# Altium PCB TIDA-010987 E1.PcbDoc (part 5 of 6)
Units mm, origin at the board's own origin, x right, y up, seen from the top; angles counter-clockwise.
Board outline 154.15 x 103.76 mm, 4 copper layers (5V, GND, MidSupply, -5V), stack 1.787 mm thick; 92 components, 52 nets, 1640 pads, 56 vias.
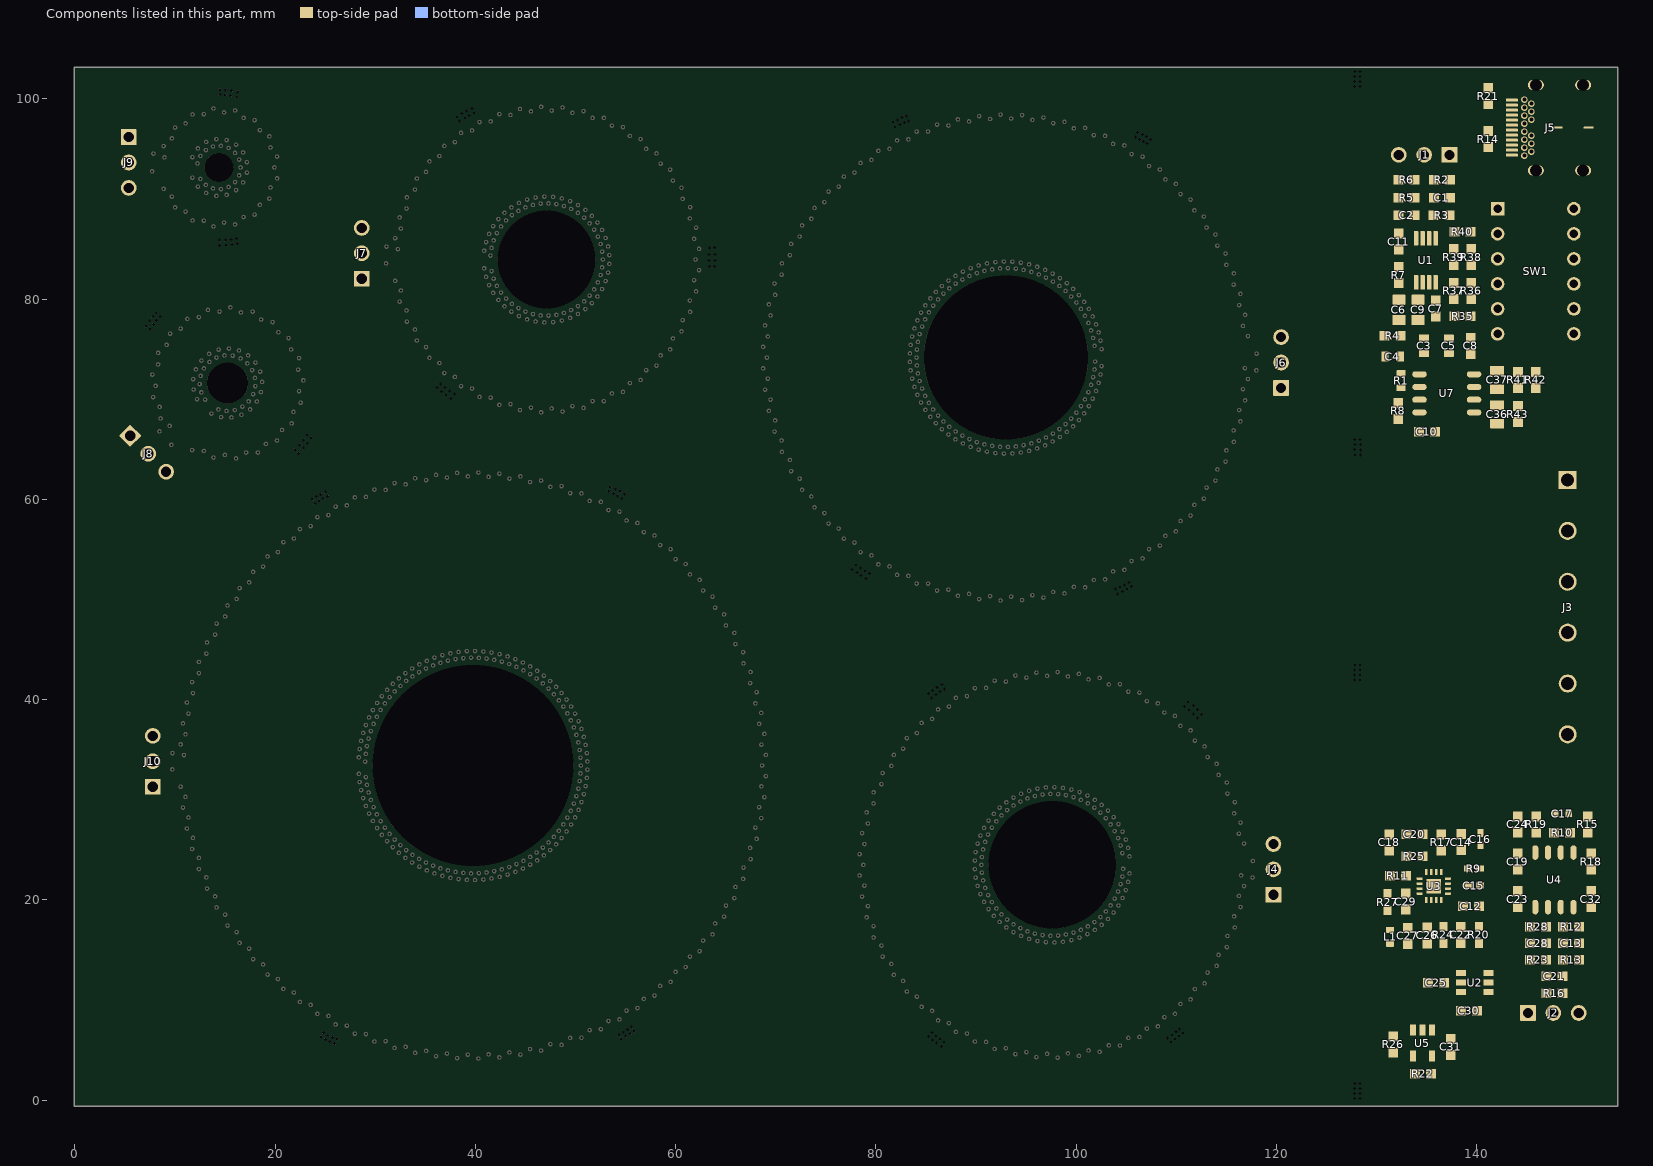
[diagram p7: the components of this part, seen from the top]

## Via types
v1: diameter 0.61, hole 0.203, 5V to -5V, tented both sides, 52 vias
v2: diameter 0.5, hole 0.2, 5V to -5V, tented both sides, 4 vias

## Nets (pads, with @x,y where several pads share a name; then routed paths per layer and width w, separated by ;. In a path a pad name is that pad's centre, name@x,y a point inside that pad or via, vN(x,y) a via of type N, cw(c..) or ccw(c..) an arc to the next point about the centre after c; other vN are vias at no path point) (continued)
copper on no net: (continued)
  -5V w0.1: 5.383,93.636 7.724,92.755 ; 5.433,93.91 7.551,93.336 7.664,93.139 12.222,93.157 ccw(c12.259,93.539) 12.363,93.91 cw(c14.398,93.14) 12.548,94.285 ; 7.331,64.551 9.646,65.446 ; 7.402,64.551 9.368,65.712 13.271,69.66 ccw(c13.022,69.953) 12.816,70.278 cw(c15.261,71.606) 12.634,70.686 ; 7.744,72.453 11.833,71.992 ; 7.828,70.199 ccw(c15.261,71.606) 8.402,68.415 ; 7.858,94.525 ccw(c14.398,93.14) 7.789,94.146 8.547,94.005 cw(c14.398,93.14) 8.755,94.913 cw(c8.883,95.276) 9.146,95.557 ; 8.086,71.337 12.48,71.501 ; 8.326,73.464 12.201,72.425 cw(c12.573,72.326) 12.698,72.69 cw(c15.261,71.606) 12.723,72.747 ccw(c12.905,73.086) 13.132,73.397 cw(c15.261,71.606) 13.446,73.715 ; 8.327,74.631 ccw(c15.261,71.606) 7.797,72.834 ccw(c7.744,72.453) 7.71,72.069 ccw(c15.261,71.606) 7.766,70.579 cw(c7.828,70.199) 8.206,70.271 11.872,70.964 ; 8.461,66.786 ccw(c15.261,71.606) 8.691,66.477 9.311,66.934 cw(c15.261,71.606) 8.761,67.735 cw(c8.573,68.071) 8.507,68.45 ; 8.484,69.234 12.271,70.559 ; 8.573,68.071 12.211,69.994 ; 8.883,91.003 ccw(c14.398,93.14) 9.777,89.447 ccw(c10.027,89.155) 10.295,88.879 ccw(c14.398,93.14) 11.423,88.027 cw(c11.762,87.845) 11.933,88.189 13.131,90.595 ; 8.883,95.276 11.747,94.166 ; 8.962,94.156 12.259,93.539 ; 9.033,95.631 cw(c14.398,93.14) 10.027,97.124 ; 9.182,75.426 12.905,73.086 ; 9.484,67.342 13.022,69.953 ; 9.527,76.54 12.646,73.856 ; 9.697,90.228 12.221,91.791 ; 9.696,96.051 12.221,94.488 ; 9.738,33.027 8.325,33.614 ; 9.761,34.657 ccw(c39.771,33.412) 9.748,34.272 10.517,34.244 cw(c39.771,33.412) 10.557,35.14 cw(c10.582,35.524) 10.641,35.904 ; 10.027,89.155 12.297,91.224 ; 10.578,77.048 13.195,74.007 cw(c13.446,73.715) 13.754,73.945 cw(c15.261,71.606) 13.807,73.979 ccw(c14.148,74.156) 14.511,74.285 cw(c15.261,71.606) 14.95,74.371 ; 10.582,31.301 ccw(c39.771,33.412) 10.758,29.581 ccw(c10.81,29.2) 10.868,28.819 ccw(c39.771,33.412) 11.11,27.498 cw(c11.19,27.121) 11.566,27.204 28.605,30.955 ; 10.582,35.524 28.368,34.237 ; 10.612,35.908 cw(c39.771,33.412) 10.81,37.625 ; 10.81,29.2 28.457,31.767 ; 10.909,34.455 29.012,33.801 ; 11.06,30.29 28.685,32.207 cw(c29.068,32.248) 29.033,32.632 cw(c39.771,33.412) 29.012,33.024 10.525,32.356 ccw(c39.771,33.412) 10.557,31.685 cw(c10.582,31.301) 10.966,31.328 28.368,32.587 ; 11.06,36.535 28.685,34.618 cw(c29.068,34.576) 29.116,34.958 cw(c39.771,33.412) 29.117,34.966 ccw(c29.18,35.346) 29.256,35.723 cw(c39.771,33.412) 29.347,36.105 ; 11.066,88.727 13.087,91.403 ; 11.066,97.553 13.087,94.876 ; 11.19,27.121 ccw(c39.771,33.412) 11.611,25.445 ccw(c11.718,25.075) 11.83,24.707 ccw(c39.771,33.412) 12.259,23.434 cw(c12.393,23.073) 12.753,23.209 29.075,29.373 ; 11.19,39.703 28.605,35.87 ; 11.236,78.011 ccw(c15.261,71.606) 9.786,76.825 ccw(c9.527,76.54) 9.284,76.242 ccw(c15.261,71.606) 8.49,74.98 cw(c8.327,74.631) 8.68,74.477 12.099,72.985 ; 11.36,28.226 29.18,31.479 ; 11.36,38.598 29.18,35.346 ; 11.718,25.075 28.812,30.155 ; 11.718,41.749 ccw(c39.771,33.412) 11.275,40.079 ccw(c11.19,39.703) 11.11,39.327 ccw(c39.771,33.412) 10.868,38.005 cw(c10.81,37.625) 11.191,37.569 28.457,35.058 ; 11.726,64.917 ccw(c15.261,71.606) 13.479,64.254 ccw(c13.855,64.172) 14.235,64.111 ccw(c15.261,71.606) 15.725,64.055 cw(c16.108,64.088) 16.065,64.471 15.648,68.177 ; 11.747,92.113 9.242,91.142 ccw(c8.883,91.003) 8.755,91.366 cw(c14.398,93.14) 8.584,92.053 12.259,92.74 ccw(c14.398,93.14) 12.375,92.338 ccw(c12.548,91.994) 12.221,91.792 ; 11.762,87.845 ccw(c14.398,93.14) 13.47,87.298 ccw(c13.852,87.25) 14.237,87.227 ccw(c14.398,93.14) 15.643,87.357 cw(c16.017,87.45) 15.912,87.821 15.176,90.405 ; 11.762,98.434 13.131,95.684 ; 11.808,26.19 28.974,30.624 cw(c29.347,30.72) 29.257,31.094 cw(c39.771,33.412) 29.256,31.102 ccw(c29.18,31.479) 29.117,31.859 cw(c39.771,33.412) 29.068,32.248 ; 11.808,40.635 28.974,36.201 cw(c29.347,36.105) 29.45,36.476 cw(c39.771,33.412) 29.452,36.483 ccw(c29.568,36.85) 29.698,37.213 cw(c39.771,33.412) 29.843,37.577 ; 12.221,94.487 cw(c12.548,94.285) 12.779,94.593 cw(c14.398,93.14) 12.802,94.618 ccw(c13.087,94.876) 13.413,95.08 cw(c14.398,93.14) 13.803,95.232 ; 12.271,70.559 cw(c12.634,70.686) 12.533,71.057 cw(c15.261,71.606) 12.521,71.119 ccw(c12.48,71.501) 12.492,71.886 cw(c15.261,71.606) 12.573,72.326 ; 12.297,95.055 10.311,96.865 ccw(c10.027,97.124) 10.295,97.4 cw(c14.398,93.14) 11.423,98.252 cw(c11.762,98.434) 12.112,98.595 cw(c14.398,93.14) 13.852,99.029 ; 12.39,78.186 14.148,74.156 ; 12.393,23.073 ccw(c39.771,33.412) 13.051,21.475 ccw(c13.21,21.124) 13.374,20.776 ccw(c39.771,33.412) 13.982,19.578 cw(c14.166,19.24) 14.503,19.426 29.768,27.876 ; 12.393,43.752 29.075,37.452 ; 12.402,24.191 29.568,29.975 ; 12.402,42.634 29.568,36.85 ; 12.548,91.994 ccw(c14.398,93.14) 12.802,91.661 cw(c13.087,91.403) 13.413,91.199 ccw(c14.398,93.14) 13.444,91.184 ; 12.885,87.821 13.697,90.676 cw(c13.803,91.047) 13.444,91.184 ; 12.885,98.458 13.697,95.603 ; 12.89,64.828 14.215,68.615 ; 13.139,22.24 29.488,29.099 cw(c29.843,29.248) 29.7,29.605 cw(c39.771,33.412) 29.698,29.612 ccw(c29.568,29.975) 29.452,30.342 cw(c39.771,33.412) 29.347,30.72 ; 13.139,44.585 29.488,37.726 cw(c29.843,37.577) 29.998,37.929 cw(c39.771,33.412) 30.001,37.936 ccw(c30.169,38.283) 30.35,38.623 cw(c39.771,33.412) 30.546,38.963 ; 13.21,21.124 29.395,28.612 ; 13.21,45.7 ccw(c39.771,33.412) 12.531,44.111 ccw(c12.393,43.752) 12.259,43.391 ccw(c39.771,33.412) 11.83,42.118 cw(c11.718,41.749) 12.087,41.64 28.812,36.669 ; 13.303,78.913 14.368,74.938 ; 13.426,74.527 11.441,77.685 ccw(c11.236,78.011) 11.568,78.207 cw(c15.261,71.606) 12.934,78.804 cw(c13.303,78.913) 13.678,79.003 cw(c15.261,71.606) 15.544,79.165 ; 13.649,68.555 11.906,65.258 ccw(c11.726,64.917) 11.391,65.106 cw(c15.261,71.606) 10.769,65.519 13.609,69.366 ccw(c15.261,71.606) 13.989,69.131 ccw(c14.342,68.979) 14.215,68.616 ; 13.697,95.602 cw(c13.803,95.232) 14.18,95.305 cw(c14.398,93.14) 14.214,95.308 ; 13.803,91.047 ccw(c14.398,93.14) 14.214,90.971 cw(c14.599,90.973) 14.977,91.042 ccw(c14.398,93.14) 15.01,91.051 ccw(c15.368,91.192) 15.54,90.847 ; 13.852,87.25 14.136,90.309 ; 13.855,64.172 14.62,68.216 ; 14.015,20.348 30.169,28.542 ; 14.015,46.477 30.169,38.283 ; 14.136,95.97 13.888,98.646 ccw(c13.852,99.029) 14.237,99.052 cw(c14.398,93.14) 15.643,98.922 cw(c16.017,98.829) 16.384,98.711 cw(c14.398,93.14) 17.963,97.86 ; 14.166,19.24 ccw(c39.771,33.412) 15.048,17.753 ccw(c15.256,17.429) 15.468,17.108 ccw(c39.771,33.412) 16.242,16.01 cw(c16.473,15.702) 16.779,15.935 30.669,26.493 ; 14.166,47.585 29.768,38.949 ; 14.214,95.308 ccw(c14.599,95.306) 14.977,95.237 cw(c14.398,93.14) 15.368,95.087 ; 14.342,68.979 ccw(c15.261,71.606) 14.775,68.865 cw(c15.157,68.824) 15.542,68.837 ccw(c15.261,71.606) 15.604,68.844 ccw(c15.982,68.917) 16.081,68.546 17.12,64.67 ; 14.457,78.74 14.907,74.754 cw(c14.95,74.371) 15.334,74.388 cw(c15.261,71.606) 15.397,74.385 ccw(c15.779,74.34) 16.151,74.243 cw(c15.261,71.606) 16.562,74.066 ; 14.599,90.973 14.908,87.633 ; 14.599,95.306 14.908,98.646 ; 14.993,64.431 15.157,68.824 ; 15.025,18.523 30.216,27.663 cw(c30.546,27.862) 30.353,28.195 cw(c39.771,33.412) 30.35,28.202 ccw(c30.169,28.542) 30.001,28.888 cw(c39.771,33.412) 29.843,29.248 ; 15.025,48.302 30.216,39.161 cw(c30.546,38.963) 30.75,39.289 cw(c39.771,33.412) 30.754,39.295 ccw(c30.97,39.614) 31.198,39.925 cw(c39.771,33.412) 31.441,40.233 ; 15.176,95.874 16.017,98.829 ; 15.256,17.429 30.194,27.168 ; 15.256,49.395 ccw(c39.771,33.412) 14.355,47.92 ccw(c14.166,47.585) 13.982,47.247 ccw(c39.771,33.412) 13.374,46.049 cw(c13.21,45.7) 13.56,45.539 29.395,38.213 ; 15.368,91.192 ccw(c14.398,93.14) 15.723,91.413 cw(c16.006,91.674) 16.239,91.979 ccw(c14.398,93.14) 16.257,92.009 ccw(c16.427,92.354) 16.786,92.215 19.555,91.142 ; 15.39,75.053 15.53,78.781 ccw(c15.544,79.165) 15.928,79.141 cw(c15.261,71.606) 17.393,78.864 cw(c17.76,78.746) 18.12,78.61 cw(c15.261,71.606) 19.754,77.692 ; 15.539,95.432 cw(c15.368,95.087) 15.696,94.886 cw(c14.398,93.14) 15.723,94.866 ccw(c16.006,94.606) 16.239,94.3 cw(c14.398,93.14) 16.427,93.926 ; 15.54,90.847 16.863,88.189 ; 15.54,95.432 16.863,98.09 ; 15.779,74.34 16.596,78.66 ; 15.982,68.917 ccw(c15.261,71.606) 16.403,69.067 cw(c16.742,69.249) 17.053,69.476 ccw(c15.261,71.606) 17.1,69.517 ccw(c17.371,69.79) 17.662,69.539 20.704,66.922 ; 16.006,91.674 18.485,89.414 ; 16.006,94.606 18.485,96.865 ; 16.017,87.45 ccw(c14.398,93.14) 17.648,88.197 ccw(c17.963,88.419) 18.262,88.661 ccw(c14.398,93.14) 19.214,89.705 cw(c19.427,90.026) 19.1,90.228 16.815,91.643 ; 16.108,64.088 ccw(c15.261,71.606) 17.93,64.527 ccw(c18.286,64.672) 18.635,64.835 ccw(c15.261,71.606) 19.898,65.628 cw(c20.196,65.871) 19.945,66.163 17.512,68.991 ; 16.111,90.871 17.963,88.419 ; 16.111,95.408 17.731,97.553 ccw(c17.963,97.86) 18.262,97.618 cw(c14.398,93.14) 19.214,96.574 cw(c19.427,96.253) 19.619,95.92 cw(c14.398,93.14) 20.212,94.226 ; 16.164,16.776 30.97,27.211 ; 16.164,50.048 30.97,39.614 ; 16.401,74.862 17.76,78.746 ; 16.427,92.353 ccw(c14.398,93.14) 16.54,92.757 cw(c16.574,93.14) 16.54,93.523 ccw(c14.398,93.14) 16.534,93.556 ccw(c16.427,93.926) 16.786,94.065 19.555,95.137 ; 16.473,15.702 ccw(c39.771,33.412) 17.559,14.358 ccw(c17.812,14.067) 18.068,13.78 ccw(c39.771,33.412) 18.992,12.804 cw(c19.265,12.533) 19.535,12.808 31.76,25.255 ; 16.473,51.123 30.669,40.331 ; 16.574,93.14 19.928,93.14 ; 16.641,68.444 18.286,64.672 ; 16.742,69.249 19.081,65.526 ; 16.815,94.636 19.427,96.253 ; 17.193,92.617 20.212,92.053 ; 17.193,93.662 19.834,94.156 ccw(c20.212,94.226) 20.271,93.846 cw(c14.398,93.14) 20.271,92.433 cw(c20.212,92.053) 20.129,91.677 cw(c14.398,93.14) 19.427,90.026 ; 17.229,73.573 20.338,76.683 ; 17.31,74.381 19.525,77.383 ccw(c19.754,77.692) 20.057,77.456 cw(c15.261,71.606) 21.112,76.402 cw(c21.348,76.098) 21.569,75.782 cw(c15.261,71.606) 22.402,74.104 ; 17.371,69.79 ccw(c15.261,71.606) 17.634,70.152 cw(c17.812,70.493) 17.941,70.855 ccw(c15.261,71.606) 17.957,70.916 ccw(c18.027,71.294) 18.409,71.251 22.396,70.802 ; 17.425,15.116 31.143,26.348 cw(c31.441,26.592) 31.202,26.894 cw(c39.771,33.412) 31.198,26.9 ccw(c30.97,27.211) 30.754,27.529 cw(c39.771,33.412) 30.546,27.862 ; 17.425,51.708 31.143,40.477 cw(c31.441,40.233) 31.69,40.526 cw(c39.771,33.412) 31.695,40.532 ccw(c31.955,40.816) 32.224,41.091 cw(c39.771,33.412) 32.509,41.361 ; 17.722,72.906 ccw(c15.261,71.606) 17.482,73.283 cw(c17.229,73.573) 16.939,73.826 ccw(c15.261,71.606) 16.889,73.863 ccw(c16.562,74.066) 16.741,74.406 18.616,77.953 ; 17.812,14.067 31.192,25.855 ; 17.812,52.758 ccw(c39.771,33.412) 16.708,51.428 ccw(c16.473,51.123) 16.242,50.815 ccw(c39.771,33.412) 15.468,49.717 cw(c15.256,49.395) 15.578,49.185 30.194,39.656 ; 17.812,70.493 21.842,68.734 ; 17.996,72.123 22.316,72.94 ; 18.027,71.294 ccw(c15.261,71.606) 18.041,71.741 cw(c17.996,72.123) 17.898,72.495 ccw(c15.261,71.606) 17.878,72.554 ccw(c17.722,72.906) 18.062,73.086 21.609,74.961 ; 18.037,73.654 21.348,76.098 ; 18.182,69.77 21.667,67.581 ; 18.518,72.745 22.038,73.977 ccw(c22.402,74.104) 22.52,73.738 cw(c15.261,71.606) 22.797,72.273 cw(c22.821,71.888) 22.826,71.503 cw(c15.261,71.606) 22.569,69.648 ; 18.594,70.713 22.197,69.747 ccw(c22.568,69.648) 22.459,69.278 cw(c15.261,71.606) 21.863,67.912 cw(c21.667,67.581) 21.454,67.26 cw(c15.261,71.606) 20.196,65.871 ; 18.709,71.735 22.821,71.888 ; 18.804,13.552 31.955,26.009 ; 18.804,53.273 31.955,40.816 ; 19.265,12.533 ccw(c39.771,33.412) 20.533,11.359 ccw(c20.825,11.108) 21.12,10.86 ccw(c39.771,33.412) 22.175,10.028 cw(c22.484,9.799) 22.711,10.109 33.017,24.187 ; 19.265,54.292 31.76,41.569 ; 20.292,12.09 32.25,25.18 cw(c32.509,25.464) 32.23,25.729 cw(c39.771,33.412) 32.224,25.734 ccw(c31.955,26.009) 31.695,26.293 cw(c39.771,33.412) 31.441,26.592 ; 20.292,54.734 32.25,41.645 cw(c32.509,41.361) 32.798,41.615 cw(c39.771,33.412) 32.804,41.62 ccw(c33.102,41.864) 33.408,42.097 cw(c39.771,33.412) 33.729,42.323 ; 20.825,11.108 32.369,24.699 ; 20.825,55.717 ccw(c39.771,33.412) 19.541,54.56 ccw(c19.265,54.292) 18.992,54.02 ccw(c39.771,33.412) 18.068,53.045 cw(c17.812,52.758) 18.101,52.503 31.192,40.97 ; 21.881,10.74 33.102,24.961 ; 21.881,56.084 33.102,41.864 ; 22.484,9.799 ccw(c39.771,33.412) 23.908,8.819 ccw(c24.233,8.613) 24.56,8.411 ccw(c39.771,33.412) 25.724,7.739 cw(c26.063,7.556) 26.243,7.897 34.415,23.311 ; 22.484,57.026 33.017,42.637 ; 23.564,9.509 33.513,24.183 cw(c33.729,24.501) 33.414,24.723 cw(c39.771,33.412) 33.408,24.728 ccw(c33.102,24.961) 32.804,25.204 cw(c39.771,33.412) 32.509,25.464 ; 23.564,57.316 33.513,42.642 cw(c33.729,42.323) 34.051,42.534 cw(c39.771,33.412) 34.058,42.538 ccw(c34.388,42.736) 34.724,42.922 cw(c39.771,33.412) 35.074,43.1 ; 24.233,8.613 33.701,23.724 ; 24.233,58.212 ccw(c39.771,33.412) 22.796,57.251 ccw(c22.484,57.026) 22.175,56.796 ccw(c39.771,33.412) 21.12,55.964 cw(c20.825,55.717) 21.074,55.424 32.369,42.126 ; 25.331,8.402 34.388,24.089 ; 25.331,58.423 34.388,42.736 ; 26.063,7.556 ccw(c39.771,33.412) 27.613,6.792 ccw(c27.964,6.635) 28.317,6.482 ccw(c39.771,33.412) 29.565,5.984 cw(c29.927,5.852) 30.057,6.215 35.925,22.646 ; 26.063,59.268 34.415,43.513 ; 27.173,7.425 34.907,23.378 cw(c35.074,23.725) 34.731,23.899 cw(c39.771,33.412) 34.724,23.902 ccw(c34.388,24.089) 34.058,24.287 cw(c39.771,33.412) 33.729,24.501 ; 27.173,59.4 34.907,43.447 cw(c35.074,43.1) 35.424,43.262 cw(c39.771,33.412) 35.431,43.265 ccw(c35.786,43.414) 36.146,43.55 cw(c39.771,33.412) 36.518,43.675 ; 27.964,6.635 35.158,22.951 ; 27.964,60.19 ccw(c39.771,33.412) 26.404,59.446 ccw(c26.063,59.268) 25.724,59.086 ccw(c39.771,33.412) 24.56,58.414 cw(c24.233,58.212) 24.437,57.886 33.701,43.101 ; 29.068,34.576 ccw(c39.771,33.412) 29.032,34.185 cw(c29.012,33.801) 29.005,33.416 9.736,33.412 8.325,33.614 ; 29.081,6.583 35.786,23.411 ; 29.081,60.241 35.786,43.414 ; 29.927,5.852 ccw(c39.771,33.412) 31.571,5.319 ccw(c31.941,5.214) 32.313,5.113 ccw(c39.771,33.412) 33.62,4.801 cw(c33.997,4.723) 34.073,5.1 37.515,22.204 ; 29.927,60.972 35.925,44.179 ; 31.045,5.882 36.401,22.782 cw(c36.518,23.15) 36.153,23.272 cw(c39.771,33.412) 36.146,23.275 ccw(c35.786,23.411) 35.431,23.56 cw(c39.771,33.412) 35.074,23.725 ; 31.045,60.943 36.401,44.042 cw(c36.518,43.675) 36.887,43.785 cw(c39.771,33.412) 36.894,43.787 ccw(c37.267,43.883) 37.643,43.966 cw(c39.771,33.412) 38.029,44.036 ; 31.087,83.562 28.661,84.562 31.082,83.947 41.501,83.954 ccw(c41.515,84.339) 41.555,84.722 cw(c47.117,83.947) 41.624,85.115 ; 31.133,85.225 ccw(c47.117,83.947) 31.107,84.841 31.875,84.787 cw(c47.117,83.947) 31.952,85.69 cw(c32.001,86.071) 32.113,86.44 ; 31.941,5.214 36.712,22.396 ; 31.941,61.611 ccw(c39.771,33.412) 30.291,61.099 ccw(c29.927,60.972) 29.565,60.84 ccw(c39.771,33.412) 28.317,60.343 cw(c27.964,60.19) 28.119,59.838 35.158,43.873 ; 32.001,81.823 ccw(c47.117,83.947) 32.342,80.111 ccw(c32.443,79.739) 32.554,79.371 ccw(c47.117,83.947) 33.02,78.092 cw(c33.172,77.738) 33.523,77.895 41.378,81.392 ; 32.001,86.071 40.896,84.821 ; 32.059,86.452 cw(c47.117,83.947) 32.443,88.155 ; 32.273,84.985 41.515,84.339 ; 32.443,79.739 41.078,82.215 ; 32.562,80.853 41.247,82.699 cw(c41.624,82.779) 41.557,83.158 cw(c47.117,83.947) 41.515,83.555 31.889,82.882 ccw(c47.117,83.947) 31.952,82.204 cw(c32.001,81.823) 32.382,81.876 40.896,83.073 ; 32.562,87.041 41.247,85.195 cw(c41.624,85.115) 41.717,85.488 cw(c47.117,83.947) 41.721,85.502 ccw(c41.84,85.868) 41.984,86.225 cw(c47.117,83.947) 42.159,86.583 ; 33.054,5.324 37.267,22.942 ; 33.054,61.5 37.267,43.883 ; 33.134,78.858 41.84,82.026 ; 33.134,89.036 41.84,85.868 ; 33.172,77.738 ccw(c47.117,83.947) 33.972,76.187 ccw(c34.172,75.858) 34.38,75.534 ccw(c47.117,83.947) 35.18,74.433 cw(c35.423,74.135) 35.718,74.382 42.304,79.909 ; 33.172,90.156 41.378,86.502 ; 33.979,76.961 41.819,81.13 cw(c42.159,81.311) 41.99,81.656 cw(c47.117,83.947) 41.984,81.669 ccw(c41.84,82.026) 41.721,82.392 cw(c47.117,83.947) 41.624,82.779 ; 33.979,90.933 41.819,86.764 cw(c42.159,86.583) 42.351,86.917 cw(c47.117,83.947) 42.358,86.929 ccw(c42.574,87.248) 42.811,87.551 cw(c47.117,83.947) 43.077,87.848 ; 33.997,4.723 ccw(c39.771,33.412) 35.7,4.432 ccw(c36.082,4.381) 36.464,4.335 ccw(c39.771,33.412) 37.802,4.214 cw(c38.186,4.19) 38.207,4.575 39.152,21.996 ; 33.997,62.102 37.515,44.62 ; 34.172,75.858 41.789,80.618 ; 34.172,92.036 ccw(c47.117,83.947) 33.333,90.506 ccw(c33.172,90.156) 33.02,89.802 ccw(c47.117,83.947) 32.554,88.523 cw(c32.443,88.155) 32.813,88.048 41.078,85.679 ; 35.079,75.201 42.574,80.646 ; 35.079,92.693 42.574,87.248 ; 35.098,4.913 37.967,22.408 cw(c38.029,22.788) 37.65,22.857 cw(c39.771,33.412) 37.643,22.859 ccw(c37.267,22.942) 36.894,23.038 cw(c39.771,33.412) 36.518,23.15 ; 35.098,61.912 37.967,44.416 cw(c38.029,44.036) 38.41,44.092 cw(c39.771,33.412) 38.417,44.093 ccw(c38.8,44.134) 39.184,44.162 cw(c39.771,33.412) 39.576,44.177 ; 35.423,74.135 ccw(c47.117,83.947) 36.62,72.864 ccw(c36.903,72.603) 37.192,72.349 ccw(c47.117,83.947) 38.264,71.511 cw(c38.581,71.292) 38.796,71.611 43.604,78.739 ; 35.423,93.759 42.304,87.985 ; 36.082,4.381 38.33,22.071 ; 36.082,62.444 ccw(c39.771,33.412) 34.374,62.176 ccw(c33.997,62.102) 33.62,62.024 ccw(c39.771,33.412) 32.313,61.711 cw(c31.941,61.611) 32.044,61.24 36.712,44.428 ; 36.413,73.61 42.8,79.779 cw(c43.077,80.046) 42.82,80.332 cw(c47.117,83.947) 42.811,80.343 ccw(c42.574,80.646) 42.358,80.965 cw(c47.117,83.947) 42.159,81.311 ; 36.413,94.284 42.8,88.115 cw(c43.077,87.848) 43.354,88.116 cw(c47.117,83.947) 43.365,88.125 ccw(c43.66,88.372) 43.971,88.599 cw(c47.117,83.947) 44.309,88.81 ; 36.903,72.603 42.913,79.278 ; 36.903,95.291 ccw(c47.117,83.947) 35.674,94.051 ccw(c35.423,93.759) 35.18,93.461 ccw(c47.117,83.947) 34.38,92.36 cw(c34.172,92.036) 34.498,91.832 41.789,87.276 ; 37.167,4.65 38.8,22.69 ; 37.167,62.175 38.8,44.134 ; 37.956,72.221 43.66,79.522 ; 37.956,95.673 43.66,88.372 ; 38.029,22.788 ccw(c39.771,33.412) 38.417,22.732 cw(c38.8,22.69) 39.184,22.662 ccw(c39.771,33.412) 39.192,22.662 ccw(c39.576,22.648) 39.569,22.263 39.249,4.537 ; 38.186,4.19 ccw(c39.771,33.412) 39.914,4.148 ccw(c40.299,4.152) 40.684,4.162 ccw(c39.771,33.412) 42.025,4.234 cw(c42.409,4.266) 42.374,4.65 40.801,22.026 ; 38.186,62.634 39.152,44.828 ; 38.33,44.754 36.13,62.062 ccw(c36.082,62.444) 36.464,62.49 cw(c39.771,33.412) 37.802,62.611 cw(c38.186,62.634) 38.571,62.653 cw(c39.771,33.412) 40.299,62.673 ; 38.581,71.292 ccw(c47.117,83.947) 40.081,70.4 ccw(c40.425,70.227) 40.773,70.063 ccw(c47.117,83.947) 42.035,69.553 cw(c42.4,69.429) 42.519,69.795 45.176,77.972 ; 38.581,96.602 43.604,89.155 ; 39.249,62.288 39.569,44.562 cw(c39.576,44.177) 39.961,44.177 cw(c39.771,33.412) 39.969,44.176 ccw(c40.354,44.163) 40.737,44.135 cw(c39.771,33.412) 41.128,44.092 ; 39.576,22.648 ccw(c39.771,33.412) 39.969,22.648 cw(c40.354,22.662) 40.737,22.69 ccw(c39.771,33.412) 40.745,22.691 ccw(c41.128,22.732) 41.176,22.35 43.411,4.763 ; 39.677,71.061 44.117,78.75 cw(c44.309,79.084) 43.983,79.287 cw(c47.117,83.947) 43.971,79.295 ccw(c43.66,79.522) 43.365,79.769 cw(c47.117,83.947) 43.077,80.046 ; 39.677,96.833 44.117,89.144 cw(c44.309,88.81) 44.649,88.991 cw(c47.117,83.947) 44.662,88.997 ccw(c45.013,89.154) 45.375,89.286 cw(c47.117,83.947) 45.758,89.396 ; 39.977,21.981 40.299,4.152 ; 39.977,44.843 40.292,62.288 ccw(c40.299,62.673) 40.684,62.663 cw(c39.771,33.412) 42.025,62.59 cw(c42.409,62.558) 42.792,62.521 cw(c39.771,33.412) 44.505,62.292 ; 40.354,22.662 41.334,4.575 ; 40.354,44.163 41.334,62.25 ; 40.425,70.227 44.363,78.3 ; 40.425,97.667 ccw(c47.117,83.947) 38.903,96.813 ccw(c38.581,96.602) 38.264,96.383 ccw(c47.117,83.947) 37.192,95.545 cw(c36.903,95.291) 37.16,95.005 42.913,88.616 ; 40.801,44.799 42.409,62.558 ; 41.128,22.732 ccw(c39.771,33.412) 41.516,22.789 cw(c41.895,22.858) 42.271,22.941 ccw(c39.771,33.412) 42.278,22.942 ccw(c42.651,23.039) 42.754,22.668 47.497,5.585 ; 41.543,70.151 45.013,78.74 ; 41.543,97.743 45.013,89.154 ; 41.62,22.13 44.505,4.533 ; 41.62,44.695 44.443,61.912 ccw(c44.505,62.292) 44.885,62.227 cw(c39.771,33.412) 46.202,61.962 cw(c46.577,61.875) 46.951,61.783 cw(c39.771,33.412) 48.613,61.31 ; 41.895,22.858 45.469,5.1 ; 41.895,43.967 45.469,61.725 ; 42.4,69.429 ccw(c47.117,83.947) 44.088,68.986 ccw(c44.466,68.914) 44.846,68.852 ccw(c47.117,83.947) 46.2,68.71 cw(c46.584,68.691) 46.598,69.076 46.898,77.668 ; 42.4,98.465 45.176,89.922 ; 42.409,4.267 ccw(c39.771,33.412) 44.125,4.473 ccw(c44.505,4.533) 44.885,4.598 ccw(c39.771,33.412) 46.202,4.863 cw(c46.577,4.95) 46.487,5.324 42.43,22.293 ; 42.43,44.532 46.577,61.875 ; 42.651,23.039 ccw(c39.771,33.412) 43.027,23.151 cw(c43.392,23.274) 43.752,23.41 ccw(c39.771,33.412) 43.759,23.412 ccw(c44.114,23.561) 44.269,23.209 51.422,6.987 ; 42.651,43.786 ccw(c39.771,33.412) 42.271,43.884 cw(c41.895,43.967) 41.516,44.036 ccw(c39.771,33.412) 41.509,44.037 ccw(c41.128,44.092) 41.176,44.474 43.411,62.062 ; 43.225,22.514 48.613,5.515 ; 43.225,44.311 48.496,60.943 ccw(c48.613,61.31) 48.979,61.191 cw(c39.771,33.412) 50.244,60.739 cw(c50.603,60.599) 50.959,60.454 cw(c39.771,33.412) 52.536,59.746 ; 43.392,23.274 49.485,6.215 ; 43.392,43.551 49.485,60.61 ; 43.517,69.509 45.665,78.125 cw(c45.758,78.498) 45.388,78.604 cw(c47.117,83.947) 45.375,78.608 ccw(c45.013,78.74) 44.662,78.897 cw(c47.117,83.947) 44.309,79.084 ; 43.517,98.385 45.665,89.769 cw(c45.758,89.396) 46.135,89.476 cw(c47.117,83.947) 46.149,89.479 ccw(c46.53,89.532) 46.914,89.559 cw(c47.117,83.947) 47.313,89.559 ; 44.002,22.791 50.46,6.583 ccw(c50.603,6.226) 50.244,6.086 cw(c39.771,33.412) 48.979,5.634 cw(c48.613,5.515) 48.245,5.401 cw(c39.771,33.412) 46.577,4.95 ; 44.002,44.033 50.603,60.599 ; 44.114,23.561 ccw(c39.771,33.412) 44.47,23.726 cw(c44.814,23.9) 45.15,24.087 ccw(c39.771,33.412) 45.157,24.091 ccw(c45.487,24.289) 45.691,23.963 55.104,8.939 ; 44.114,43.263 ccw(c39.771,33.412) 43.752,43.415 cw(c43.392,43.551) 43.027,43.674 ccw(c39.771,33.412) 43.02,43.676 ccw(c42.651,43.786) 42.754,44.157 47.497,61.24 ; 44.363,89.594 40.594,97.321 ccw(c40.425,97.667) 40.773,97.831 cw(c47.117,83.947) 42.035,98.341 cw(c42.4,98.465) 42.767,98.579 cw(c47.117,83.947) 44.466,98.98 ; 44.466,68.914 46.026,77.76 ; 44.758,23.125 52.536,7.078 ; 44.758,43.7 52.368,59.4 ccw(c52.536,59.746) 52.882,59.576 cw(c39.771,33.412) 54.068,58.947 cw(c54.403,58.757) 54.735,58.562 cw(c39.771,33.412) 56.194,57.635 ; 44.814,23.9 53.298,7.897 ; 44.814,42.924 53.298,58.928 ; 45.487,23.511 54.211,8.402 ccw(c54.403,8.068) 54.068,7.878 cw(c39.771,33.412) 52.882,7.249 cw(c52.536,7.078) 52.189,6.913 cw(c39.771,33.412) 50.603,6.226 ; 45.487,24.289 ccw(c39.771,33.412) 45.816,24.504 cw(c46.13,24.725) 46.437,24.958 ccw(c39.771,33.412) 46.443,24.963 ccw(c46.74,25.207) 46.99,24.913 58.467,11.401 ; 45.487,42.536 ccw(c39.771,33.412) 45.15,42.738 cw(c44.814,42.924) 44.47,43.098 ccw(c39.771,33.412) 44.463,43.102 ccw(c44.114,43.263) 44.269,43.616 51.422,59.838 ; 45.487,43.313 54.403,58.757 ; 45.562,69.149 46.53,78.362 ; 45.562,98.745 46.53,89.532 ; 45.758,78.498 ccw(c47.117,83.947) 46.149,78.415 cw(c46.53,78.362) 46.914,78.335 ccw(c47.117,83.947) 46.928,78.335 ccw(c47.313,78.335) 47.326,77.95 47.636,69.076 ; 46.026,90.134 44.533,98.601 ccw(c44.466,98.98) 44.846,99.042 cw(c47.117,83.947) 46.2,99.184 cw(c46.584,99.203) 46.969,99.211 cw(c47.117,83.947) 48.713,99.128 ; 46.13,24.725 56.83,10.109 ; 46.13,42.099 56.83,56.715 ; 46.187,23.95 56.194,9.19 ; 46.187,42.875 55.978,57.316 ccw(c56.194,57.635) 56.511,57.417 cw(c39.771,33.412) 57.595,56.623 cw(c57.899,56.386) 58.199,56.146 cw(c39.771,33.412) 59.509,55.018 ; 46.584,68.691 ccw(c47.117,83.947) 48.329,68.73 ccw(c48.713,68.766) 49.095,68.811 ccw(c47.117,83.947) 50.435,69.047 cw(c50.81,69.135) 50.717,69.509 48.637,77.851 ; 46.584,99.203 46.898,90.226 ; 46.74,25.207 ccw(c39.771,33.412) 47.035,25.466 cw(c47.314,25.731) 47.584,26.006 ccw(c39.771,33.412) 47.589,26.011 ccw(c47.849,26.296) 48.138,26.041 61.441,14.321 ; 46.74,41.618 ccw(c39.771,33.412) 46.437,41.866 cw(c46.13,42.099) 45.816,42.321 ccw(c39.771,33.412) 45.809,42.325 ccw(c45.487,42.536) 45.691,42.862 55.104,57.886 ; 46.853,24.437 57.66,10.74 ccw(c57.899,10.438) 57.595,10.202 cw(c39.771,33.412) 56.511,9.408 cw(c56.194,9.19) 55.874,8.976 cw(c39.771,33.412) 54.403,8.068 ; 46.853,42.388 57.899,56.386 ; 47.313,78.335 ccw(c47.117,83.947) 47.711,78.363 cw(c48.092,78.417) 48.469,78.496 ccw(c47.117,83.947) 48.482,78.5 ccw(c48.852,78.606) 48.971,78.24 51.715,69.795 ; 47.314,25.731 60.007,12.808 ; 47.314,41.093 60.007,54.017 ; 47.482,24.972 59.509,11.806 ; 47.482,41.853 59.25,54.734 ccw(c59.509,55.018) 59.792,54.757 cw(c39.771,33.412) 60.75,53.816 cw(c61.017,53.538) 61.28,53.257 cw(c39.771,33.412) 62.414,51.952 ; 47.636,98.818 47.326,89.944 cw(c47.313,89.559) 47.697,89.533 cw(c47.117,83.947) 47.711,89.531 ccw(c48.092,89.477) 48.469,89.398 cw(c47.117,83.947) 48.852,89.288 ; 47.774,77.699 48.713,68.766 ; 47.774,90.195 48.672,98.745 ccw(c48.713,99.128) 49.095,99.083 cw(c47.117,83.947) 50.435,98.847 cw(c50.81,98.759) 51.182,98.661 cw(c47.117,83.947) 52.835,98.1 ; 47.849,26.296 ccw(c39.771,33.412) 48.103,26.595 cw(c48.341,26.897) 48.569,27.208 ccw(c39.771,33.412) 48.573,27.214 ccw(c48.789,27.532) 49.112,27.322 63.963,17.639 ; 47.849,40.529 ccw(c39.771,33.412) 47.584,40.819 cw(c47.314,41.093) 47.035,41.358 ccw(c39.771,33.412) 47.029,41.363 ccw(c46.74,41.618) 46.99,41.911 58.467,55.424 ; 48.071,25.55 60.737,13.552 ccw(c61.017,13.287) 60.75,13.009 cw(c39.771,33.412) 59.792,12.068 cw(c59.509,11.806) 59.223,11.548 cw(c39.771,33.412) 57.899,10.438 ; 48.071,41.275 61.017,53.538 ; 48.092,78.417 49.701,69.293 ; 48.092,89.477 49.701,98.601 ; 48.341,26.897 62.762,15.935 ; 48.341,39.928 62.762,50.89 ; 48.617,26.169 62.414,14.872 ; 48.617,40.655 62.116,51.708 ccw(c62.414,51.952) 62.656,51.653 cw(c39.771,33.412) 63.469,50.583 cw(c63.693,50.27) 63.912,49.954 cw(c39.771,33.412) 64.847,48.5 ; 48.637,90.043 50.81,98.759 ; 48.789,27.532 ccw(c39.771,33.412) 48.998,27.865 cw(c49.19,28.199) 49.37,28.539 ccw(c39.771,33.412) 49.374,28.545 ccw(c49.542,28.892) 49.891,28.73 65.981,21.286 ; 48.789,39.292 ccw(c39.771,33.412) 48.569,39.617 cw(c48.341,39.928) 48.103,40.23 ccw(c39.771,33.412) 48.098,40.236 ccw(c47.849,40.529) 48.138,40.784 61.441,52.503 ; 48.852,78.606 ccw(c47.117,83.947) 49.227,78.743 cw(c49.579,78.9) 49.919,79.08 ccw(c47.117,83.947) 49.931,79.087 ccw(c50.257,79.291) 50.472,78.972 55.438,71.611 ; 49.116,26.827 63.378,16.776 ccw(c63.693,16.555) 63.469,16.241 cw(c39.771,33.412) 62.656,15.172 cw(c62.414,14.872) 62.168,14.576 cw(c39.771,33.412) 61.017,13.287 ; 49.116,39.998 63.693,50.27 ; 49.19,28.199 65.038,19.426 ; 49.19,38.626 65.038,47.398 ; 49.47,78.122 52.835,69.794 ; 49.47,89.772 52.691,97.743 ccw(c52.835,98.1) 53.19,97.952 cw(c47.117,83.947) 54.414,97.355 cw(c54.749,97.167) 55.08,96.97 cw(c47.117,83.947) 56.515,95.976 ; 49.542,28.892 ccw(c39.771,33.412) 49.7,29.251 cw(c49.842,29.609) 49.972,29.971 ccw(c39.771,33.412) 49.974,29.978 ccw(c50.091,30.345) 50.46,30.236 67.454,25.185 ; 49.542,37.933 ccw(c39.771,33.412) 49.37,38.286 cw(c49.19,38.626) 48.998,38.96 ccw(c39.771,33.412) 48.994,38.966 ccw(c48.789,39.292) 49.112,39.502 63.963,49.185 ; 49.567,27.518 64.847,18.325 ; 49.567,39.307 64.517,48.302 ccw(c64.847,48.5) 65.043,48.169 cw(c39.771,33.412) 65.693,46.993 cw(c65.87,46.651) 66.042,46.307 cw(c39.771,33.412) 66.757,44.733 ; 49.579,78.9 53.64,70.573 ; 49.579,88.994 53.64,97.321 ; 49.842,29.609 66.788,23.209 ; 49.842,37.216 66.788,43.616 ; 49.967,28.24 65.527,20.348 ccw(c65.87,20.173) 65.693,19.831 cw(c39.771,33.412) 65.043,18.656 cw(c64.847,18.325) 64.646,17.996 cw(c39.771,33.412) 63.693,16.555 ; 49.967,38.584 65.87,46.651 ; 50.091,30.345 ccw(c39.771,33.412) 50.195,30.724 cw(c50.285,31.098) 50.361,31.475 ccw(c39.771,33.412) 50.362,31.483 ccw(c50.425,31.863) 50.806,31.807 68.35,29.255 ; 50.091,36.479 ccw(c39.771,33.412) 49.972,36.853 cw(c49.842,37.216) 49.7,37.574 ccw(c39.771,33.412) 49.697,37.581 ccw(c49.542,37.933) 49.891,38.095 65.981,45.539 ; 50.257,79.291 ccw(c47.117,83.947) 50.58,79.526 cw(c50.875,79.774) 51.152,80.041 ccw(c47.117,83.947) 51.161,80.051 ccw(c51.419,80.337) 51.714,80.09 58.516,74.382 ; 50.257,88.603 ccw(c47.117,83.947) 49.919,88.814 cw(c49.579,88.994) 49.227,89.151 ccw(c47.117,83.947) 49.214,89.156 ccw(c48.852,89.288) 48.971,89.654 51.715,98.099 ; 50.258,78.506 54.557,71.061 ccw(c54.749,70.727) 54.414,70.539 cw(c47.117,83.947) 53.19,69.942 cw(c52.835,69.794) 52.477,69.654 cw(c47.117,83.947) 50.81,69.135 ; 50.258,89.388 54.749,97.167 ; 50.285,31.098 67.975,27.204 ; 50.285,35.727 67.975,39.621 ; 50.313,28.99 66.757,22.091 ; 50.313,37.835 66.402,44.585 ccw(c66.757,44.733) 66.904,44.377 cw(c39.771,33.412) 67.378,43.121 cw(c67.504,42.757) 67.624,42.391 cw(c39.771,33.412) 68.106,40.731 ; 50.425,31.863 ccw(c39.771,33.412) 50.474,32.252 cw(c50.509,32.635) 50.529,33.02 ccw(c39.771,33.412) 50.53,33.027 ccw(c50.537,33.412) 50.922,33.412 68.651,33.412 ; 50.425,34.962 ccw(c39.771,33.412) 50.361,35.349 cw(c50.285,35.727) 50.195,36.101 ccw(c39.771,33.412) 50.194,36.108 ccw(c50.091,36.479) 50.46,36.589 67.454,41.64 ; 50.509,32.635 68.575,31.328 ; 50.509,34.189 68.575,35.496 ; 50.537,33.412 ccw(c39.771,33.412) 50.529,33.805 cw(c50.509,34.189) 50.474,34.573 ccw(c39.771,33.412) 50.473,34.58 ccw(c50.425,34.962) 50.806,35.017 68.35,37.569 ; 50.605,29.762 67.139,24.191 ccw(c67.504,24.068) 67.378,23.704 cw(c39.771,33.412) 66.904,22.447 cw(c66.757,22.091) 66.606,21.737 cw(c39.771,33.412) 65.87,20.173 ; 50.605,37.063 67.504,42.757 ; 50.84,30.553 68.106,26.093 ; 50.84,36.272 67.733,40.635 ccw(c68.106,40.731) 68.2,40.358 cw(c39.771,33.412) 68.488,39.046 cw(c68.56,38.668) 68.627,38.288 cw(c39.771,33.412) 68.864,36.576 ; 50.875,79.774 57.074,72.889 ; 50.875,88.12 57.074,95.005 ; 50.985,78.996 56.515,71.918 ; 50.985,88.898 56.278,95.673 ccw(c56.515,95.976) 56.815,95.735 cw(c47.117,83.947) 57.827,94.825 cw(c58.098,94.551) 58.362,94.271 cw(c47.117,83.947) 59.467,92.92 ; 51.018,31.359 68.181,28.226 ccw(c68.56,28.157) 68.488,27.779 cw(c39.771,33.412) 68.2,26.467 cw(c68.106,26.093) 68.007,25.721 cw(c39.771,33.412) 67.504,24.068 ; 51.018,35.465 68.56,38.668 ; 51.136,32.176 68.864,30.248 ; 51.136,34.648 68.481,36.535 ccw(c68.864,36.576) 68.903,36.193 cw(c39.771,33.412) 69,34.854 cw(c69.017,34.469) 69.028,34.084 cw(c39.771,33.412) 69.017,32.356 ; 51.196,33 68.632,32.37 ccw(c69.017,32.356) 69,31.971 cw(c39.771,33.412) 68.903,30.631 cw(c68.864,30.248) 68.82,29.866 cw(c39.771,33.412) 68.56,28.157 ; 51.196,33.825 69.017,34.469 ; 51.419,80.337 ccw(c47.117,83.947) 51.664,80.652 cw(c51.879,80.971) 52.072,81.304 ccw(c47.117,83.947) 52.079,81.317 ccw(c52.247,81.663) 52.599,81.506 60.711,77.895 ; 51.419,87.557 ccw(c47.117,83.947) 51.152,87.853 cw(c50.875,88.12) 50.58,88.368 ccw(c47.117,83.947) 50.569,88.377 ccw(c50.257,88.603) 50.472,88.922 55.438,96.283 ; 51.636,79.583 57.821,73.61 ccw(c58.098,73.343) 57.827,73.069 cw(c47.117,83.947) 56.815,72.159 cw(c56.515,71.918) 56.209,71.685 cw(c47.117,83.947) 54.75,70.727 ; 51.636,88.311 58.098,94.551 ; 51.879,80.971 59.736,76.062 ; 51.879,86.923 59.736,91.832 ; 52.2,80.254 59.467,74.974 ; 52.2,87.64 59.155,92.693 ccw(c59.467,92.92) 59.689,92.605 cw(c47.117,83.947) 60.41,91.451 cw(c60.595,91.113) 60.772,90.771 cw(c47.117,83.947) 61.461,89.168 ; 52.247,81.663 ccw(c47.117,83.947) 52.396,82.033 cw(c52.515,82.399) 52.608,82.773 ccw(c47.117,83.947) 52.611,82.786 ccw(c52.678,83.165) 53.059,83.112 61.852,81.876 ; 52.247,86.231 ccw(c47.117,83.947) 52.072,86.59 cw(c51.879,86.923) 51.664,87.242 ccw(c47.117,83.947) 51.656,87.254 ccw(c51.419,87.557) 51.714,87.804 58.516,93.512 ; 52.515,82.399 61.421,79.846 ; 52.515,85.495 61.421,88.048 ; 52.664,80.998 60.255,76.961 ccw(c60.595,76.781) 60.41,76.443 cw(c47.117,83.947) 59.689,75.289 cw(c59.467,74.974) 59.236,74.666 cw(c47.117,83.947) 58.098,73.343 ; 52.664,86.896 60.595,91.113 ; 52.678,83.165 ccw(c47.117,83.947) 52.719,83.562 cw(c52.733,83.947) 52.719,84.332 ccw(c47.117,83.947) 52.719,84.346 ccw(c52.678,84.729) 53.059,84.782 61.852,86.018 ; 52.678,84.729 ccw(c47.117,83.947) 52.608,85.121 cw(c52.515,85.495) 52.396,85.861 ccw(c47.117,83.947) 52.392,85.874 ccw(c52.247,86.231) 52.599,86.388 60.711,89.999 ; 52.733,83.947 61.997,83.947 ; 53.021,81.798 61.461,78.726 ; 53.021,86.096 61.1,89.036 ccw(c61.461,89.168) 61.589,88.805 cw(c47.117,83.947) 61.964,87.496 cw(c62.048,87.121) 62.124,86.743 cw(c47.117,83.947) 62.345,85.012 ; 53.262,82.641 61.672,80.853 ccw(c62.048,80.773) 61.964,80.398 cw(c47.117,83.947) 61.589,79.089 cw(c61.461,78.726) 61.325,78.366 cw(c47.117,83.947) 60.595,76.781 ; 53.262,85.253 62.048,87.121 ; 53.384,83.509 62.345,82.882 ; 53.384,84.385 61.961,84.985 ccw(c62.345,85.012) 62.367,84.627 cw(c47.117,83.947) 62.367,83.267 cw(c62.345,82.882) 62.313,82.498 cw(c47.117,83.947) 62.048,80.773 ; 68.755,73.079 83.412,73.728 ; 68.755,75.226 ccw(c92.996,74.152) 68.741,73.464 ccw(c68.755,73.079) 68.775,72.695 ccw(c92.996,74.152) 68.897,71.323 cw(c68.945,70.941) 69.326,70.992 83.487,72.883 ; 68.945,70.941 ccw(c92.996,74.152) 69.241,69.204 ccw(c69.323,68.828) 69.41,68.453 ccw(c92.996,74.152) 69.772,67.124 cw(c69.886,66.756) 70.253,66.874 83.859,71.228 ; 68.945,77.364 83.487,75.422 ; 69.116,74.152 83.685,74.152 cw(c84.07,74.152) 84.078,74.537 cw(c92.996,74.152) 84.079,74.557 ccw(c84.105,74.941) 84.147,75.324 cw(c92.996,74.152) 84.209,75.724 ; 69.21,72.042 84.105,73.364 ; 69.21,76.263 84.105,74.941 ; 69.323,68.828 83.637,72.047 ; 69.323,79.477 ccw(c92.996,74.152) 68.999,77.745 ccw(c68.945,77.364) 68.897,76.982 ccw(c92.996,74.152) 68.775,75.61 cw(c68.755,75.226) 69.14,75.209 83.412,74.577 ; 69.489,69.948 83.83,72.513 cw(c84.209,72.581) 84.15,72.961 cw(c92.996,74.152) 84.147,72.981 ccw(c84.105,73.364) 84.079,73.748 cw(c92.996,74.152) 84.07,74.152 ; 69.489,78.357 83.83,75.792 cw(c84.209,75.724) 84.285,76.102 cw(c92.996,74.152) 84.29,76.121 ccw(c84.382,76.495) 84.491,76.864 cw(c92.996,74.152) 84.623,77.247 ; 69.886,66.756 ccw(c92.996,74.152) 70.484,65.099 ccw(c70.63,64.743) 70.782,64.389 ccw(c92.996,74.152) 71.372,63.145 cw(c71.549,62.803) 71.89,62.983 84.517,69.665 ; 69.886,81.549 83.859,77.077 ; 69.953,67.887 84.382,71.81 ; 69.953,80.418 84.382,76.495 ; 70.597,65.875 84.262,70.925 cw(c84.623,71.058) 84.498,71.422 cw(c92.996,74.152) 84.491,71.441 ccw(c84.382,71.81) 84.29,72.184 cw(c92.996,74.152) 84.209,72.581 ; 70.597,82.43 84.262,77.38 cw(c84.623,77.247) 84.764,77.605 cw(c92.996,74.152) 84.772,77.623 ccw(c84.929,77.975) 85.102,78.319 cw(c92.996,74.152) 85.299,78.673 ; 70.63,64.743 84.154,70.432 ; 70.63,83.562 ccw(c92.996,74.152) 70.006,81.914 ccw(c69.886,81.549) 69.772,81.181 ccw(c92.996,74.152) 69.41,79.852 cw(c69.323,79.477) 69.698,79.393 83.637,76.258 ; 71.416,63.928 84.929,70.33 ; 71.416,84.377 84.929,77.975 ; 71.549,62.803 ccw(c92.996,74.152) 72.429,61.277 ccw(c72.636,60.952) 72.848,60.63 ccw(c92.996,74.152) 73.648,59.509 cw(c73.883,59.204) 74.186,59.441 85.44,68.242 ; 71.549,85.502 84.517,78.64 ; 72.404,62.06 84.967,69.437 cw(c85.299,69.632) 85.111,69.968 cw(c92.996,74.152) 85.102,69.986 ccw(c84.929,70.33) 84.772,70.682 cw(c92.996,74.152) 84.623,71.058 ; 72.404,86.245 84.967,78.868 cw(c85.299,78.673) 85.501,79 cw(c92.996,74.152) 85.512,79.017 ccw(c85.728,79.335) 85.959,79.644 cw(c92.996,74.152) 86.215,79.957 ; 72.636,60.952 84.947,68.933 ; 72.636,87.353 ccw(c92.996,74.152) 71.732,85.841 ccw(c71.549,85.502) 71.372,85.16 ccw(c92.996,74.152) 70.782,83.916 cw(c70.63,83.562) 70.985,83.413 84.154,77.873 ; 73.554,60.288 85.728,68.97 ; 73.554,88.017 85.728,79.335 ; 73.883,59.204 ccw(c92.996,74.152) 75.018,57.856 ccw(c75.279,57.573) 75.544,57.294 ccw(c92.996,74.152) 76.528,56.331 cw(c76.813,56.072) 77.07,56.359 86.598,67.004 ; 73.883,89.101 85.44,80.063 ; 74.855,58.624 85.922,68.097 cw(c86.215,68.348) 85.971,68.645 ; 74.855,89.681 85.922,80.208 cw(c86.215,79.957) 86.472,80.244 cw(c92.996,74.152) 86.485,80.259 ccw(c86.754,80.534) 87.035,80.797 cw(c92.996,74.152) 87.343,81.061 ; 75.279,57.573 85.991,67.598 ; 75.279,90.732 ccw(c92.996,74.152) 74.122,89.402 ccw(c73.883,89.101) 73.648,88.796 ccw(c92.996,74.152) 72.848,87.675 cw(c72.636,87.353) 72.959,87.144 84.947,79.372 ; 76.298,57.081 86.754,67.771 ; 76.298,91.224 86.754,80.534 ; 76.813,56.072 ccw(c92.996,74.152) 78.168,54.946 ccw(c78.474,54.713) 78.785,54.485 ccw(c92.996,74.152) 79.923,53.71 cw(c80.249,53.505) 80.452,53.833 87.957,65.989 ; 76.813,92.233 86.598,81.301 ; 77.873,55.672 87.099,66.946 cw(c87.343,67.244) 87.05,67.494 cw(c92.996,74.152) 87.035,67.508 ccw(c86.754,67.771) 86.485,68.046 cw(c92.996,74.152) 86.215,68.348 ; 77.873,92.633 87.099,81.359 cw(c87.343,81.061) 87.646,81.298 cw(c92.996,74.152) 87.662,81.31 ccw(c87.976,81.533) 88.298,81.743 cw(c92.996,74.152) 88.648,81.948 ; 78.392,22.431 ccw(c97.628,23.493) 78.566,20.702 ccw(c78.626,20.322) 78.693,19.943 ccw(c97.628,23.493) 78.989,18.622 cw(c79.09,18.251) 79.461,18.355 90.167,21.383 ; 78.392,24.554 89.886,23.92 ; 78.474,54.713 87.255,66.467 ; 78.474,93.592 ccw(c92.996,74.152) 77.102,92.487 ccw(c76.813,92.233) 76.528,91.974 ccw(c92.996,74.152) 75.544,91.011 cw(c75.279,90.732) 75.56,90.469 85.991,80.707 ; 78.626,20.322 89.98,22.216 ; 78.626,26.664 ccw(c97.628,23.493) 78.418,24.938 ccw(c78.392,24.554) 78.375,24.169 ccw(c97.628,23.493) 78.375,22.816 cw(c78.392,22.431) 78.777,22.453 89.886,23.065 ; 78.748,23.493 90.541,23.493 ; 78.863,21.416 90.201,22.671 cw(c90.584,22.713) 90.552,23.097 cw(c97.628,23.493) 90.551,23.108 ccw(c90.541,23.493) 90.551,23.877 cw(c97.628,23.493) 90.584,24.272 ; 78.863,25.57 90.201,24.315 cw(c90.584,24.272) 90.637,24.654 cw(c97.628,23.493) 90.639,24.665 ccw(c90.713,25.042) 90.807,25.416 cw(c97.628,23.493) 90.925,25.794 ; 79.09,18.251 ccw(c97.628,23.493) 79.638,16.601 ccw(c79.779,16.243) 79.928,15.888 ccw(c97.628,23.493) 80.505,14.664 cw(c80.685,14.324) 81.024,14.507 90.809,19.802 ; 79.09,28.735 90.167,25.603 ; 79.205,19.364 90.713,21.943 ; 79.205,27.621 90.713,25.042 ; 79.565,54.408 87.976,66.772 ; 79.565,93.897 87.976,81.533 ; 79.771,17.362 90.561,21.066 cw(c90.925,21.191) 90.81,21.559 cw(c97.628,23.493) 90.807,21.57 ccw(c90.713,21.943) 90.639,22.321 cw(c97.628,23.493) 90.584,22.713 ; 79.771,29.623 90.561,25.919 cw(c90.925,25.794) 91.06,26.154 cw(c97.628,23.493) 91.064,26.165 ccw(c91.219,26.517) 91.393,26.861 cw(c97.628,23.493) 91.59,27.204 ; 79.779,16.243 90.444,20.575 ; 79.779,30.742 ccw(c97.628,23.493) 79.199,29.104 ccw(c79.09,28.735) 78.989,28.363 ccw(c97.628,23.493) 78.693,27.043 cw(c78.626,26.664) 79.006,26.6 89.98,24.769 ; 80.249,53.505 ccw(c92.996,74.152) 81.781,52.635 ccw(c82.124,52.46) 82.47,52.29 ccw(c92.996,74.152) 83.727,51.728 cw(c84.084,51.584) 84.225,51.942 89.473,65.23 ; 80.249,94.8 87.957,82.316 ; 80.554,15.435 91.219,20.468 ; 80.554,31.55 91.219,26.517 ; 80.685,14.324 ccw(c97.628,23.493) 81.58,12.834 ccw(c81.797,12.515) 82.019,12.201 ccw(c97.628,23.493) 82.85,11.133 cw(c83.1,10.84) 83.391,11.093 91.781,18.4 ; 80.685,32.662 90.809,27.183 ; 81.363,53.298 88.46,66.021 cw(c88.648,66.357) 88.315,66.552 cw(c92.996,74.152) 88.298,66.562 ccw(c87.976,66.772) 87.662,66.995 cw(c92.996,74.152) 87.343,67.244 ; 81.363,95.007 88.46,82.284 cw(c88.648,81.948) 88.988,82.128 cw(c92.996,74.152) 89.006,82.137 ccw(c89.354,82.302) 89.708,82.451 cw(c92.996,74.152) 90.088,82.592 ; 81.544,13.606 91.263,19.58 cw(c91.59,19.781) 91.398,20.115 cw(c97.628,23.493) 91.393,20.124 ccw(c91.219,20.468) 91.064,20.82 cw(c97.628,23.493) 90.925,21.191 ; 81.544,33.38 91.263,27.406 cw(c91.59,27.204) 91.801,27.526 cw(c97.628,23.493) 91.807,27.536 ccw(c92.035,27.846) 92.28,28.143 cw(c97.628,23.493) 92.548,28.435 ; 81.797,12.515 91.256,19.074 ; 81.797,34.47 ccw(c97.628,23.493) 80.872,32.999 ccw(c80.685,32.662) 80.505,32.321 ccw(c97.628,23.493) 79.928,31.097 cw(c79.779,30.742) 80.136,30.597 90.444,26.411 ; 82.124,52.46 88.698,65.576 ; 82.124,95.845 ccw(c92.996,74.152) 80.579,94.999 ccw(c80.249,94.8) 79.923,94.595 ccw(c92.996,74.152) 78.785,93.82 cw(c78.474,93.592) 78.705,93.284 87.255,81.838 ; 82.729,11.896 92.035,19.14 ; 82.729,35.089 92.035,27.846 ; 83.1,10.84 ccw(c97.628,23.493) 84.3,9.582 ccw(c84.58,9.319) 84.866,9.061 ccw(c97.628,23.493) 85.911,8.201 cw(c86.219,7.97) 86.447,8.28 93.036,17.245 ; 83.1,36.145 91.781,28.585 ; 83.251,52.351 89.354,66.003 ; 83.251,95.954 89.354,82.302 ; 84.084,51.584 ccw(c92.996,74.152) 85.745,50.996 ccw(c86.113,50.884) 86.483,50.778 ccw(c92.996,74.152) 87.82,50.446 cw(c88.197,50.367) 88.273,50.744 91.099,64.749 ; 84.084,96.721 89.473,83.075 ; 84.095,10.328 92.272,18.282 cw(c92.548,18.551) 92.287,18.834 cw(c97.628,23.493) 92.28,18.842 ccw(c92.035,19.14) 91.807,19.45 cw(c97.628,23.493) 91.59,19.781 ; 84.095,36.658 92.272,28.703 cw(c92.548,28.435) 92.824,28.703 cw(c97.628,23.493) 92.832,28.711 ccw(c93.123,28.963) 93.426,29.2 cw(c97.628,23.493) 93.752,29.426 ; 84.58,9.319 92.377,17.788 ; 84.58,37.666 ccw(c97.628,23.493) 83.356,36.433 ccw(c83.1,36.145) 82.85,35.852 ccw(c97.628,23.493) 82.019,34.784 cw(c81.797,34.47) 82.113,34.251 91.256,27.911 ; 85.216,51.575 89.963,65.349 cw(c90.088,65.713) 89.727,65.846 cw(c92.996,74.152) 89.708,65.854 ccw(c89.354,66.003) 89.006,66.168 cw(c92.996,74.152) 88.648,66.357 ; 85.216,96.73 89.963,82.956 cw(c90.088,82.592) 90.455,82.71 cw(c92.996,74.152) 90.474,82.715 ccw(c90.845,82.816) 91.221,82.901 cw(c92.996,74.152) 91.619,82.972 ; 85.299,69.632 ccw(c92.996,74.152) 85.512,69.288 cw(c85.728,68.97) 85.959,68.661 ccw(c92.996,74.152) 85.971,68.645 ; 85.626,8.919 93.123,18.022 ; 85.626,38.066 93.123,28.963 ; 86.113,50.884 90.275,64.953 ; 86.113,97.421 ccw(c92.996,74.152) 84.443,96.86 ccw(c84.084,96.721) 83.727,96.577 ccw(c92.996,74.152) 82.47,96.015 cw(c82.124,95.845) 82.296,95.501 88.698,82.729 ; 86.219,7.97 ccw(c97.628,23.493) 87.664,7.004 ccw(c87.996,6.809) 88.331,6.62 ccw(c97.628,23.493) 89.539,6.008 cw(c89.89,5.85) 90.044,6.203 94.513,16.392 ; 86.219,39.016 93.036,29.741 ; 87.242,50.976 90.845,65.489 ; 87.242,97.329 90.845,82.816 ; 87.302,7.687 93.541,17.237 cw(c93.752,17.559) 93.435,17.779 cw(c97.628,23.493) 93.426,17.785 ccw(c93.123,18.022) 92.832,18.275 cw(c97.628,23.493) 92.548,18.551 ; 87.302,39.298 93.541,29.748 cw(c93.752,29.426) 94.08,29.628 cw(c97.628,23.493) 94.089,29.633 ccw(c94.428,29.816) 94.776,29.981 cw(c97.628,23.493) 95.143,30.13 ; 87.996,6.809 93.751,16.777 ; 87.996,40.177 ccw(c97.628,23.493) 86.531,39.241 ccw(c86.219,39.016) 85.911,38.785 ccw(c97.628,23.493) 84.866,37.924 cw(c84.58,37.666) 84.841,37.383 92.377,29.197 ; 88.197,50.367 ccw(c92.996,74.152) 89.935,50.081 ccw(c90.318,50.036) 90.701,49.996 ccw(c92.996,74.152) 92.075,49.905 cw(c92.46,49.893) 92.468,50.278 92.784,64.561 ; 88.197,97.938 91.099,83.556 ; 89.103,6.647 94.428,17.169 ; 89.103,40.338 94.428,29.816 ; 89.313,50.558 91.56,64.952 cw(c91.619,65.333) 91.24,65.4 cw(c92.996,74.152) 91.221,65.404 ccw(c90.845,65.489) 90.474,65.59 cw(c92.996,74.152) 90.088,65.713 ; 89.313,97.747 91.56,83.353 cw(c91.619,82.972) 92.001,83.023 cw(c92.996,74.152) 92.021,83.026 ccw(c92.404,83.059) 92.789,83.077 cw(c92.996,74.152) 93.194,83.077 ; 89.89,5.85 ccw(c97.628,23.493) 91.511,5.225 ccw(c91.877,5.106) 92.246,4.995 ccw(c97.628,23.493) 93.558,4.663 cw(c93.935,4.585) 94.009,4.963 96.142,15.882 ; 89.89,41.135 94.513,30.594 ; 90.275,83.352 86.222,97.052 ccw(c86.113,97.421) 86.483,97.527 cw(c92.996,74.152) 87.82,97.859 cw(c88.197,97.938) 88.575,98.011 cw(c92.996,74.152) 90.318,98.269 ; 90.318,50.036 91.937,64.618 ; 91.008,5.811 95.008,16.495 cw(c95.143,16.855) 94.786,17 cw(c97.628,23.493) 94.776,17.005 ccw(c94.428,17.169) 94.089,17.352 cw(c97.628,23.493) 93.752,17.559 ; 91.008,41.174 95.008,30.49 cw(c95.143,30.13) 95.507,30.255 cw(c97.628,23.493) 95.518,30.258 ccw(c95.888,30.363) 96.264,30.447 cw(c97.628,23.493) 96.655,30.513 ; 91.413,50.325 92.404,65.246 ; 91.413,97.98 92.404,83.059 ; 91.619,65.333 ccw(c92.996,74.152) 92.021,65.279 cw(c92.404,65.246) 92.789,65.228 ccw(c92.996,74.152) 92.809,65.228 ccw(c93.194,65.228) 93.202,64.843 93.525,50.278 ; 91.877,5.106 95.314,16.092 ; 91.877,41.879 ccw(c97.628,23.493) 90.244,41.286 ccw(c89.89,41.135) 89.539,40.977 ccw(c97.628,23.493) 88.331,40.366 cw(c87.996,40.177) 88.188,39.843 93.751,30.208 ; 91.937,83.687 90.36,97.887 ccw(c90.318,98.269) 90.701,98.309 cw(c92.996,74.152) 92.075,98.4 cw(c92.46,98.412) 92.845,98.417 cw(c92.996,74.152) 94.606,98.364 ; 92.46,49.893 ccw(c92.996,74.152) 94.221,49.918 ccw(c94.606,49.941) 94.99,49.969 ccw(c92.996,74.152) 96.358,50.122 cw(c96.739,50.178) 96.68,50.558 94.476,64.674 ; 92.46,98.412 92.784,83.744 ; 92.993,5.19 95.888,16.622 ; 92.993,41.795 95.888,30.363 ; 93.194,65.228 ccw(c92.996,74.152) 93.598,65.246 cw(c93.982,65.28) 94.363,65.331 ccw(c92.996,74.152) 94.383,65.334 ccw(c94.762,65.402) 94.838,65.025 97.72,50.744 ; 93.525,98.027 93.202,83.462 cw(c93.194,83.077) 93.578,83.06 cw(c92.996,74.152) 93.598,83.059 ccw(c93.982,83.025) 94.363,82.974 cw(c92.996,74.152) 94.762,82.903 ; 93.633,64.58 94.606,49.941 ; 93.633,83.725 94.58,97.98 ccw(c94.606,98.364) 94.99,98.335 cw(c92.996,74.152) 96.358,98.183 cw(c96.739,98.127) 97.119,98.065 cw(c92.996,74.152) 98.843,97.702 ; 93.935,4.585 ccw(c97.628,23.493) 95.654,4.329 ccw(c96.037,4.293) 96.421,4.265 ccw(c97.628,23.493) 97.774,4.228 cw(c98.159,4.235) 98.148,4.62 97.842,15.742 ; 93.935,42.4 96.142,31.103 ; 93.982,65.28 95.633,50.418 ; 93.982,83.025 95.633,97.887 ; 94.476,83.631 96.739,98.127 ; 94.762,65.402 ccw(c92.996,74.152) 95.157,65.491 cw(c95.528,65.593) 95.895,65.71 ccw(c92.996,74.152) 95.914,65.716 ccw(c96.275,65.85) 96.416,65.492 101.767,51.942 ; 95.035,4.792 96.602,16.091 cw(c96.655,16.473) 96.275,16.536 cw(c97.628,23.493) 96.264,16.538 ccw(c95.888,16.622) 95.518,16.727 cw(c97.628,23.493) 95.143,16.855 ; 95.035,42.194 96.602,30.894 cw(c96.655,30.513) 97.037,30.555 cw(c97.628,23.493) 97.049,30.556 ccw(c97.433,30.577) 97.818,30.577 cw(c97.628,23.493) 98.213,30.556 ; 95.308,64.842 98.843,50.602 ; 95.308,83.463 98.751,97.329 ccw(c98.843,97.702) 99.216,97.607 cw(c92.996,74.152) 100.537,97.216 cw(c100.902,97.094) 101.265,96.965 cw(c92.996,74.152) 102.898,96.305 ; 95.314,30.893 91.992,41.512 ccw(c91.877,41.879) 92.246,41.991 cw(c97.628,23.493) 93.558,42.323 cw(c93.935,42.4) 94.313,42.47 cw(c97.628,23.493) 96.037,42.692 ; 95.528,65.593 99.77,51.253 ; 95.528,82.712 99.77,97.052 ; 96.037,4.293 96.988,15.765 ; 96.122,65.082 100.776,51.575 ccw(c100.902,51.211) 100.537,51.089 cw(c92.996,74.152) 99.216,50.698 cw(c98.843,50.602) 98.469,50.513 cw(c92.996,74.152) 96.739,50.178 ; 96.122,83.222 100.902,97.094 ; 96.275,65.85 ccw(c92.996,74.152) 96.648,66.007 cw(c96.996,66.172) 97.336,66.352 ccw(c92.996,74.152) 97.354,66.362 ccw(c97.686,66.557) 97.888,66.229 105.541,53.833 ; 96.275,82.455 ccw(c92.996,74.152) 95.895,82.595 cw(c95.528,82.712) 95.157,82.814 ccw(c92.996,74.152) 95.138,82.818 ccw(c94.762,82.903) 94.838,83.28 97.72,97.561 ; 96.655,16.473 ccw(c97.628,23.493) 97.049,16.429 cw(c97.433,16.408) 97.818,16.408 ccw(c97.628,23.493) 97.829,16.408 ccw(c98.213,16.43) 98.245,16.046 99.187,4.677 ; 96.911,65.394 102.898,52 ; 96.911,82.911 102.741,95.954 ccw(c102.898,96.305) 103.249,96.145 cw(c92.996,74.152) 104.48,95.528 cw(c104.818,95.343) 105.152,95.153 cw(c92.996,74.152) 106.644,94.216 ; 96.988,31.22 96.069,42.308 ccw(c96.037,42.692) 96.421,42.72 cw(c97.628,23.493) 97.774,42.757 cw(c98.159,42.75) 98.544,42.736 cw(c97.628,23.493) 100.274,42.575 ; 96.996,66.172 103.696,52.804 ; 96.996,82.133 103.696,95.501 ; 97.108,4.62 97.433,16.408 ; 97.108,42.365 97.433,30.577 ; 97.67,65.774 104.63,53.298 ccw(c104.818,52.962) 104.48,52.777 cw(c92.996,74.152) 103.249,52.16 cw(c102.898,52) 102.546,51.846 cw(c92.996,74.152) 100.902,51.211 ; 97.67,82.53 104.818,95.343 ; 97.686,66.557 ccw(c92.996,74.152) 98.025,66.777 cw(c98.339,67.001) 98.642,67.238 ccw(c92.996,74.152) 98.657,67.251 ccw(c98.95,67.501) 99.207,67.214 108.923,56.359 ; 97.686,81.748 ccw(c92.996,74.152) 97.336,81.953 cw(c96.996,82.133) 96.648,82.298 ccw(c92.996,74.152) 96.63,82.306 ccw(c96.275,82.455) 96.416,82.813 101.767,96.363 ; 97.842,31.244 98.159,42.75 ; 98.159,4.235 ccw(c97.628,23.493) 99.892,4.361 ccw(c100.274,4.41) 100.655,4.467 ccw(c97.628,23.493) 101.983,4.726 cw(c102.357,4.817) 102.263,5.19 99.532,15.976 ; 98.213,16.43 ccw(c97.628,23.493) 98.607,16.473 cw(c98.987,16.537) 99.363,16.621 ccw(c97.628,23.493) 99.373,16.624 ccw(c99.744,16.729) 99.859,16.361 103.264,5.473 ; 98.339,67.001 107.288,55.021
